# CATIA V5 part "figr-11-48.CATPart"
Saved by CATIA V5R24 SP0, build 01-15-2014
Part number: Part1
Bounding box of the stored display mesh (mm): x -270.607 to 0, y -223.278 to 0, z -13.562 to 46.691
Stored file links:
  D:\KAVITA\CATIA V5-6R2014 Project_ Kavita\CATIA V5-6R2014_partfiles\Partfiles\c11_catia_v5-6r2014_prt\figr-11-48.CATPart
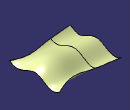
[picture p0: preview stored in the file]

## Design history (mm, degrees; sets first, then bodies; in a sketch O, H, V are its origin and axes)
Set1
  Sweep1: type Unspec, Profile Sketch2, Guide Sketch1
  Extrapol1: ToExtrapol edge of Sweep1, Support Sweep1, Length 100
Body1 (main body)
  Sketch1 on yz-plane, origin (0, 0, 0), H (0, 1, 0), V (0, 0, 1)
    spline S1 through (0, 0) (-40, -10) (-100, 20) (-170, 0) (-220, 10)
    point P1 (0, 0)
    coincidence: P1 O
  Sketch2 on zx-plane, origin (0, 0, 0), H (-1, 0, 0), V (0, 0, 1)
    spline S1 through (0, 0) (60, 30) (121.1814, 19.9844) (171.1814, 9.9844)
    point P1 (0, 0)
    coincidence: P1 O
